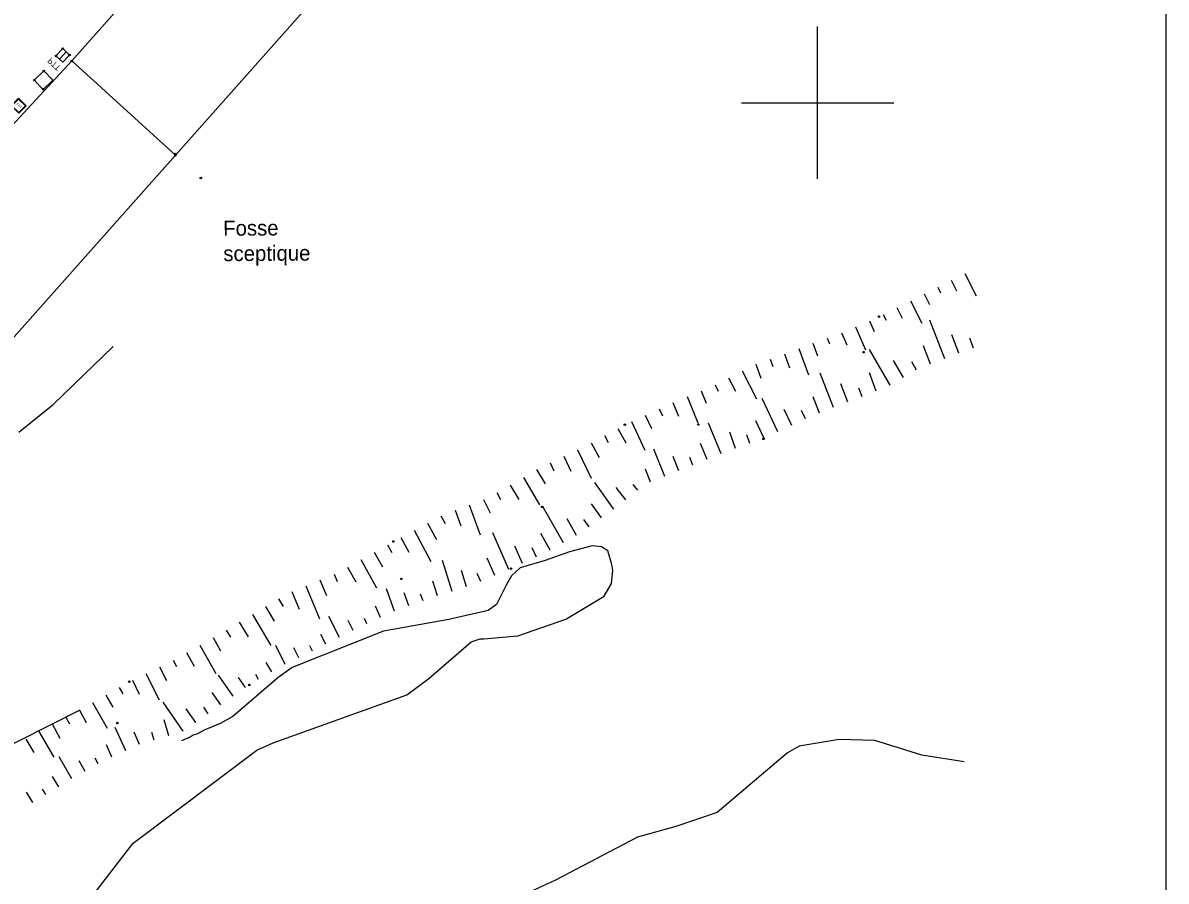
# Model space of a CAD drawing. Extents: x 344013 to 344423, y 298505 to 298795.
# Drawn here: x 344347.8 to 344422.9, y 298548.8 to 298605.2 of the extents above; entities that cross this region are included whole.
import ezdxf

# ---------------------------------------------------------------- set-up
doc = ezdxf.new("R2010")
doc.units = 0
for name, color, linetype in [('Default', 7, 'Continuous'), ('DH_CADRE -CARTOUCHE', 7, 'Continuous'), ('DH_CADRE-CARTOUCHE-NORD', 7, 'Continuous'), ('PS_BOLT', 7, 'Continuous'), ('PS_CONST', 7, 'Continuous'), ('RES_ELECTRICITE', 7, 'Continuous'), ('TOPO_COURBE NIVEAU', 7, 'Continuous'), ('TOPO_POINT', 7, 'Continuous'), ('TOPO_TALUS-TERRAIN NATUREL', 7, 'Continuous')]:
    doc.layers.add(name, color=color, linetype=linetype)

# ---------------------------------------------------------------- blocks, each defined once
blk = doc.blocks.new('RES_ELECTRICITE')
at = {"layer": 'RES_ELECTRICITE'}
for points in [[(0, 0), (0, 1), (1, 1), (1, 0)], [(0.05, 0.05), (0.05, 0.95), (0.95, 0.95), (0.95, 0.05)]]:
    blk.add_lwpolyline(points, close=True, dxfattribs=at)
blk.add_text('EEC', height=0.2, dxfattribs=at).set_placement((0.24, 0.46))
blk = doc.blocks.new('CT2')
at = {"layer": 'Default'}
blk.add_lwpolyline([(0, 0), (1, 0), (1, 1), (0, 1)], close=True, dxfattribs=at)
blk.add_lwpolyline([(0.5, 1), (0.5, 0)], dxfattribs=at)
blk.add_text('PTT', height=0.6, dxfattribs=at).set_placement((-0.3, 1.43))
blk = doc.blocks.new('POINT_DISPLAY')
at = {"layer": 'Default'}
blk.add_circle((0, 0), 0.05, dxfattribs=at)

msp = doc.modelspace()

# ---------------------------------------------------------------- linework, layer by layer
at = {"layer": 'DH_CADRE -CARTOUCHE'}
msp.add_lwpolyline([(344012.906, 298504.876), (344422.906, 298504.876), (344422.906, 298791.876), (344012.906, 298791.876)], close=True, dxfattribs=at)
msp.add_lwpolyline([(344357.784, 298596.545), (344357.784, 298596.545), (344333.772, 298569.519), (344326.819, 298575.802), (344346.771, 298598.198), (344350.978, 298602.747), (344357.784, 298596.545)], dxfattribs=at)
at = {"layer": 'DH_CADRE-CARTOUCHE-NORD'}
for p, q in [((344400, 298595), (344400, 298605)), ((344395, 298600), (344405, 298600))]:
    msp.add_line(p, q, dxfattribs=at)
at = {"layer": 'PS_BOLT'}
for points in [[(344361.238, 298614.297), (344350.978, 298602.747), (344357.784, 298596.545), (344368.087, 298608.155)], [(344349.102, 298600.877), (344348.509, 298601.488), (344349.138, 298602.09), (344349.732, 298601.479)]]:
    msp.add_lwpolyline(points, close=True, dxfattribs=at)
at = {"layer": 'TOPO_COURBE NIVEAU'}
for points in [[(344347.492, 298578.337), (344349.752, 298580.151), (344353.694, 298583.97)], [(344352.414, 298547.972), (344355.001, 298551.319), (344363.146, 298557.424), (344364.207, 298557.905), (344372.997, 298561.081), (344374.443, 298562.135), (344377.229, 298564.547), (344377.812, 298564.752), (344378.064, 298564.751), (344380.298, 298564.942), (344383.443, 298566.044), (344385.969, 298567.55), (344386.457, 298568.4), (344386.536, 298569.237), (344386.48, 298569.638), (344386.212, 298570.535), (344385.795, 298570.81), (344385.181, 298570.873), (344383.694, 298570.471), (344382.08, 298569.894), (344380.442, 298569.422), (344379.875, 298568.886), (344379.53, 298568.272), (344378.891, 298567.018), (344378.342, 298566.625), (344375.768, 298566.017), (344371.465, 298565.267), (344365.456, 298562.872), (344364.512, 298562.196), (344361.562, 298559.636), (344360.735, 298559.187), (344359.666, 298558.745), (344359.241, 298558.509), (344358.957, 298558.414), (344358.879, 298558.383), (344358.745, 298558.281), (344358.187, 298558.036)], [(344331.843, 298549.826), (344334.381, 298551.346), (344334.853, 298551.975), (344335.883, 298554.171), (344336.378, 298554.573), (344337.991, 298555.18), (344345.561, 298557.088), (344351.519, 298560.091)], [(344409.625, 298556.657), (344406.838, 298557.096), (344403.759, 298558.078), (344401.404, 298558.132), (344398.791, 298557.706), (344398.021, 298557.249), (344393.394, 298553.342), (344390.688, 298552.413), (344388.156, 298551.703), (344382.767, 298548.891), (344377.062, 298546.251)]]:
    msp.add_lwpolyline(points, dxfattribs=at)
at = {"layer": 'TOPO_TALUS-TERRAIN NATUREL'}
for p, q in [((344409.68, 298588.771), (344410.414, 298587.31)), ((344407.892, 298587.874), (344408.076, 298587.508)), ((344408.786, 298588.323), (344409.134, 298587.629)), ((344406.998, 298587.425), (344407.347, 298586.73)), ((344405.21, 298586.528), (344405.56, 298585.831)), ((344406.104, 298586.977), (344406.84, 298585.509)), ((344403.405, 298585.667), (344403.713, 298584.95)), ((344404.316, 298586.08), (344404.5, 298585.712)), ((344408.358, 298583.17), (344407.366, 298585.713)), ((344401.567, 298584.878), (344401.91, 298584.079)), ((344402.486, 298585.273), (344403.136, 298583.758)), ((344399.692, 298584.18), (344399.993, 298583.362)), ((344400.631, 298584.526), (344400.773, 298584.138)), ((344409.29, 298583.533), (344408.819, 298584.741)), ((344410.233, 298583.867), (344410.011, 298584.514)), ((344397.814, 298583.49), (344398.148, 298582.579)), ((344398.753, 298583.835), (344399.388, 298582.109)), ((344404.769, 298581.426), (344403.411, 298583.781)), ((344407.426, 298582.806), (344406.956, 298584.011)), ((344395.936, 298582.801), (344396.271, 298581.888)), ((344396.875, 298583.145), (344397.051, 298582.665)), ((344405.636, 298581.926), (344404.991, 298583.044)), ((344406.502, 298582.426), (344406.196, 298582.957)), ((344394.148, 298581.906), (344394.592, 298581.039)), ((344395.038, 298582.362), (344395.974, 298580.535)), ((344401.052, 298579.957), (344400.156, 298582.222)), ((344403.856, 298581.025), (344403.399, 298582.23)), ((344392.341, 298581.052), (344392.673, 298580.238)), ((344393.258, 298581.45), (344393.469, 298581.038)), ((344401.985, 298580.316), (344401.53, 298581.518)), ((344402.921, 298580.671), (344402.704, 298581.241)), ((344390.489, 298580.295), (344390.859, 298579.39)), ((344391.415, 298580.674), (344392.116, 298578.957)), ((344397.389, 298578.352), (344396.346, 298580.542)), ((344400.122, 298579.589), (344399.697, 298580.663)), ((344389.579, 298579.881), (344389.796, 298579.413)), ((344398.292, 298578.782), (344397.797, 298579.822)), ((344399.195, 298579.212), (344398.934, 298579.761)), ((344387.764, 298579.039), (344388.636, 298577.162)), ((344388.671, 298579.46), (344389.084, 298578.571)), ((344393.658, 298576.922), (344392.836, 298578.935)), ((344396.486, 298577.922), (344395.937, 298579.075)), ((344385.992, 298578.111), (344386.24, 298577.655)), ((344386.871, 298578.588), (344387.392, 298577.629)), ((344394.597, 298577.265), (344394.223, 298578.35)), ((344395.542, 298577.591), (344395.345, 298578.163)), ((344385.113, 298577.633), (344385.636, 298576.672)), ((344392.732, 298576.544), (344392.299, 298577.604)), ((344383.316, 298576.757), (344383.787, 298575.767)), ((344384.219, 298577.187), (344385.112, 298575.311)), ((344389.95, 298575.418), (344389.224, 298577.227)), ((344390.878, 298575.79), (344390.496, 298576.745)), ((344391.805, 298576.166), (344391.6, 298576.668)), ((344381.52, 298575.877), (344382.081, 298574.933)), ((344382.412, 298576.327), (344382.661, 298575.805)), ((344389.021, 298575.046), (344388.678, 298575.903)), ((344380.66, 298575.366), (344381.727, 298573.573)), ((344386.607, 298573.285), (344385.348, 298575.036)), ((344378.92, 298574.38), (344379.159, 298573.914)), ((344379.8, 298574.854), (344380.363, 298573.908)), ((344387.395, 298573.9), (344386.765, 298574.707)), ((344388.183, 298574.516), (344387.884, 298574.899)), ((344377.102, 298573.554), (344377.826, 298571.587)), ((344378.03, 298573.923), (344378.483, 298573.04)), ((344385.794, 298572.701), (344385.132, 298573.623)), ((344375.236, 298572.839), (344375.512, 298572.325)), ((344376.164, 298573.208), (344376.545, 298572.171)), ((344383.286, 298571.063), (344381.99, 298573.375)), ((344374.355, 298572.365), (344374.938, 298571.281)), ((344384.159, 298571.552), (344383.543, 298572.65)), ((344384.982, 298572.117), (344384.633, 298572.602)), ((344372.593, 298571.417), (344373.118, 298570.44)), ((344373.474, 298571.891), (344374.581, 298569.832)), ((344379.696, 298569.303), (344378.655, 298571.729)), ((344382.413, 298570.574), (344381.799, 298571.67)), ((344371.716, 298570.937), (344372.002, 298570.426)), ((344380.608, 298569.714), (344380.087, 298570.855)), ((344381.518, 298570.13), (344381.243, 298570.732)), ((344369.971, 298569.958), (344371.004, 298568.115)), ((344370.843, 298570.447), (344371.387, 298569.477)), ((344375.967, 298567.867), (344375.342, 298569.903)), ((344378.777, 298568.908), (344378.284, 298570.058)), ((344369.098, 298569.469), (344369.644, 298568.497)), ((344376.923, 298568.161), (344376.593, 298569.235)), ((344377.858, 298568.514), (344377.624, 298569.058)), ((344367.286, 298568.628), (344367.715, 298567.597)), ((344368.21, 298569.012), (344368.413, 298568.523)), ((344375.011, 298567.573), (344374.715, 298568.538)), ((344365.439, 298567.861), (344365.916, 298566.713)), ((344366.362, 298568.245), (344367.266, 298566.068)), ((344372.181, 298566.577), (344371.662, 298568.033)), ((344373.123, 298566.912), (344372.819, 298567.766)), ((344374.065, 298567.248), (344373.905, 298567.698)), ((344363.704, 298566.868), (344364.279, 298565.905)), ((344364.564, 298567.38), (344364.866, 298566.873)), ((344371.274, 298566.155), (344370.929, 298566.893)), ((344362.845, 298566.356), (344364.058, 298564.323)), ((344368.573, 298564.847), (344367.877, 298566.221)), ((344370.367, 298565.732), (344370.204, 298566.082)), ((344361.127, 298565.331), (344361.4, 298564.873)), ((344361.986, 298565.844), (344362.562, 298564.878)), ((344369.465, 298565.3), (344369.135, 298565.952)), ((344360.258, 298564.835), (344360.76, 298563.954)), ((344367.681, 298564.395), (344367.351, 298565.046)), ((344358.52, 298563.846), (344359.022, 298562.963)), ((344359.389, 298564.341), (344360.447, 298562.481)), ((344364.99, 298563.067), (344364.381, 298564.306)), ((344365.888, 298563.508), (344365.567, 298564.162)), ((344366.786, 298563.949), (344366.616, 298564.294)), ((344357.645, 298563.361), (344357.859, 298562.928)), ((344364.118, 298562.579), (344363.751, 298563.206)), ((344355.852, 298562.475), (344356.708, 298560.741)), ((344356.748, 298562.918), (344357.199, 298562.005)), ((344361.584, 298560.976), (344360.611, 298562.367)), ((344363.254, 298562.074), (344363.061, 298562.404)), ((344354.08, 298561.548), (344354.319, 298561.127)), ((344354.955, 298562.031), (344355.407, 298561.117)), ((344362.403, 298561.549), (344361.942, 298562.209)), ((344353.21, 298561.053), (344353.665, 298560.254)), ((344360.764, 298560.403), (344360.195, 298561.216)), ((344351.471, 298560.064), (344351.927, 298559.263)), ((344352.341, 298560.558), (344353.301, 298558.871)), ((344358.304, 298558.684), (344356.976, 298560.583)), ((344359.124, 298559.257), (344358.494, 298560.159)), ((344359.944, 298559.83), (344359.645, 298560.258)), ((344350.587, 298559.596), (344350.814, 298559.165)), ((344357.353, 298558.383), (344357.038, 298559.436)), ((344348.818, 298558.662), (344349.801, 298556.978)), ((344349.702, 298559.13), (344350.181, 298558.222)), ((344354.527, 298557.393), (344353.826, 298558.923)), ((344355.436, 298557.81), (344355.066, 298558.617)), ((344356.394, 298558.097), (344356.245, 298558.596)), ((344347.954, 298558.158), (344348.473, 298557.27)), ((344353.617, 298556.977), (344353.248, 298557.782)), ((344350.983, 298555.544), (344350.15, 298556.998)), ((344351.851, 298556.041), (344351.455, 298556.732)), ((344352.719, 298556.539), (344352.51, 298556.903)), ((344350.126, 298555.028), (344349.715, 298555.707)), ((344349.271, 298554.509), (344349.054, 298554.867)), ((344348.416, 298553.99), (344348, 298554.665))]:
    msp.add_line(p, q, dxfattribs=at)

# ---------------------------------------------------------------- block references
at = {"layer": 'DH_CADRE-CARTOUCHE-NORD', "xscale": 0.6128420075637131, "yscale": -0.655630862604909, "rotation": -43.213050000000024}
msp.add_blockref('CT2', (344350.383, 298603.554), dxfattribs=at)
at = {"layer": 'RES_ELECTRICITE', "xscale": 0.7140719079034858, "yscale": 0.6822477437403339, "rotation": -44.364193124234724}
msp.add_blockref('RES_ELECTRICITE', (344346.991, 298599.804), dxfattribs=at)
at = {"layer": 'TOPO_POINT'}
for p in [(344350.383, 298603.554), (344349.938, 298603.072), (344350.829, 298603.134), (344349.138, 298602.09), (344350.978, 298602.747), (344348.509, 298601.488), (344349.102, 298600.877), (344357.776, 298596.63), (344357.784, 298596.545), (344359.455, 298595.047), (344404.024, 298585.933), (344403.026, 298583.597), (344387.325, 298578.835), (344392.163, 298578.846), (344396.443, 298577.902), (344381.892, 298573.429), (344372.103, 298571.154), (344379.851, 298569.369), (344372.631, 298568.694), (344354.763, 298561.936), (344362.646, 298561.719), (344353.965, 298559.217)]:
    msp.add_blockref('POINT_DISPLAY', p, dxfattribs=at)

# ---------------------------------------------------------------- texts
at = {"layer": 'PS_CONST'}
for s, p in [('Fosse', (344360.927, 298591.25)), ('sceptique', (344360.938, 298589.583)), ('sceptique', (344360.938, 298589.583))]:
    msp.add_text(s, height=1.0003, rotation=0.36648, dxfattribs=at).set_placement(p)

doc.saveas('drawing.dxf')
